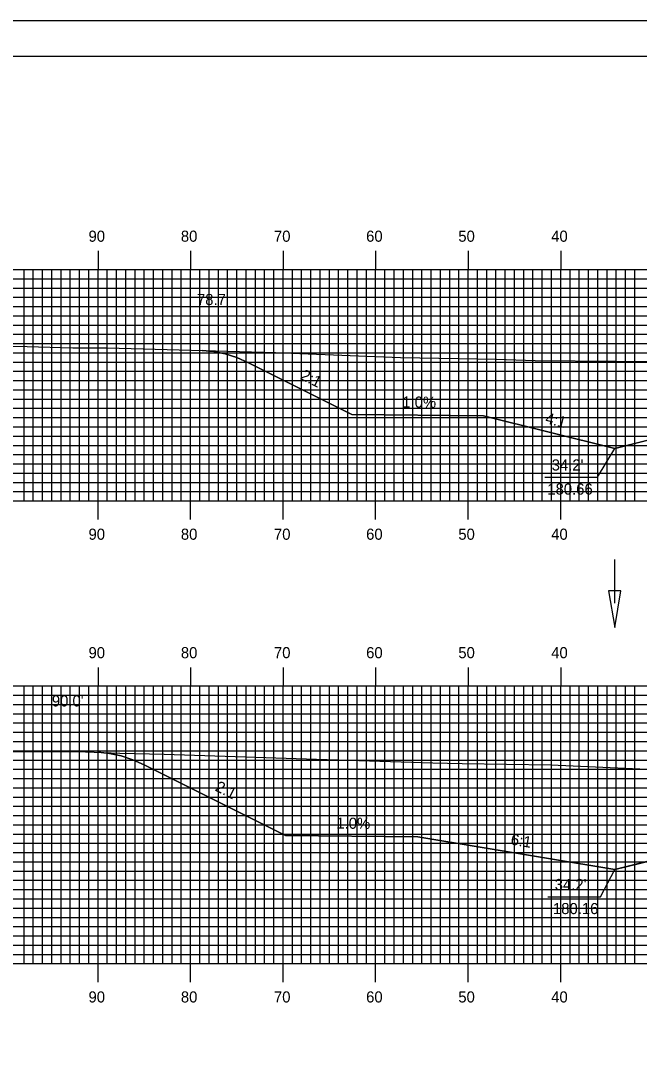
# Model space of a CAD drawing. Extents: x 1797207 to 1797550, y 442591 to 442811.
# Drawn here: x 1797274.6 to 1797341.4, y 442698.3 to 442810.5 of the extents above; entities that cross this region are included whole.
import ezdxf

# ---------------------------------------------------------------- set-up
doc = ezdxf.new("R2010")
doc.units = 0
for name, color, linetype in [('ANNOTATION', 7, 'Continuous'), ('BORDER', 7, 'Continuous'), ('D_Drainage_Ditch_Line', 7, 'Continuous'), ('D_Roadway_Centerline', 7, 'Continuous'), ('D_Roadway_SlopeLines', 7, 'Continuous'), ('D_Text_Standard', 7, 'Continuous'), ('H_V ANNOTATION', 7, 'Continuous'), ('MAJOR', 7, 'Continuous'), ('MINOR', 7, 'Continuous'), ('PLOT BOUNDARY', 7, 'Continuous'), ('S_Roadway_Centerline', 7, 'Continuous')]:
    doc.layers.add(name, color=color, linetype=linetype)

msp = doc.modelspace()

# ---------------------------------------------------------------- linework, layer by layer
at = {"layer": 'ANNOTATION'}
for points in [[(1797331.21, 442761.23), (1797336.9, 442761.23), (1797338.76, 442764.33)], [(1797331.55, 442715.89), (1797337.24, 442715.89), (1797338.76, 442718.83)]]:
    msp.add_lwpolyline(points, dxfattribs=at)
at = {"layer": 'BORDER'}
msp.add_lwpolyline([(1797223.33, 442596.67), (1797543.33, 442596.67), (1797543.33, 442806.67), (1797223.33, 442806.67)], close=True, dxfattribs=at)
at = {"layer": 'D_Drainage_Ditch_Line'}
msp.add_line((1797338.76, 442747.63), (1797338.76, 442752.33), dxfattribs=at)
msp.add_lwpolyline([(1797339.41, 442748.94), (1797338.1, 442748.94), (1797338.76, 442745)], close=True, dxfattribs=at)
at = {"layer": 'D_Roadway_Centerline'}
for points in [[(1797294.18, 442774.92), (1797295.43, 442774.81), (1797296.68, 442774.55), (1797297.93, 442774.15), (1797299.18, 442773.6), (1797310.36, 442768.01), (1797324.58, 442767.87), (1797338.76, 442764.33), (1797342.76, 442765.33), (1797352.93, 442767.87), (1797360.93, 442768.19), (1797372.93, 442767.95), (1797384.93, 442767.71), (1797392.93, 442767.39), (1797403.11, 442764.85), (1797407.11, 442763.85), (1797421.28, 442767.39), (1797440.76, 442767.58), (1797446.68, 442770.54), (1797447.93, 442771.08), (1797449.18, 442771.45), (1797450.43, 442771.65), (1797451.68, 442771.68)], [(1797282.93, 442731.5), (1797284.18, 442731.38), (1797285.43, 442731.11), (1797286.68, 442730.7), (1797287.93, 442730.15), (1797303.2, 442722.51), (1797317.5, 442722.37), (1797338.76, 442718.83), (1797342.76, 442719.83), (1797352.93, 442722.37), (1797360.93, 442722.69), (1797372.93, 442722.45), (1797384.93, 442722.21), (1797392.93, 442721.89)]]:
    msp.add_lwpolyline(points, dxfattribs=at)
at = {"layer": 'D_Roadway_SlopeLines'}
for points in [[(1797324.58, 442767.87), (1797310.36, 442768.01), (1797299.18, 442773.6), (1797297.93, 442774.15), (1797296.68, 442774.55), (1797295.43, 442774.81), (1797294.18, 442774.92)], [(1797338.76, 442764.33), (1797324.58, 442767.87)], [(1797352.93, 442767.87), (1797338.76, 442764.33)], [(1797317.5, 442722.37), (1797303.2, 442722.51), (1797287.93, 442730.15), (1797286.68, 442730.7), (1797285.43, 442731.11), (1797284.18, 442731.38), (1797282.93, 442731.5)], [(1797338.76, 442718.83), (1797317.5, 442722.37)], [(1797352.93, 442722.37), (1797338.76, 442718.83)]]:
    msp.add_lwpolyline(points, dxfattribs=at)
at = {"layer": 'MAJOR'}
for p, q in [((1797282.93, 442785.67), (1797282.93, 442783.67)), ((1797292.93, 442785.67), (1797292.93, 442783.67)), ((1797302.93, 442785.67), (1797302.93, 442783.67)), ((1797312.93, 442785.67), (1797312.93, 442783.67)), ((1797322.93, 442785.67), (1797322.93, 442783.67)), ((1797332.93, 442785.67), (1797332.93, 442783.67)), ((1797232.93, 442783.67), (1797512.93, 442783.67)), ((1797232.93, 442783.67), (1797512.93, 442783.67)), ((1797282.93, 442758.67), (1797282.93, 442783.67)), ((1797292.93, 442758.67), (1797292.93, 442783.67)), ((1797302.93, 442758.67), (1797302.93, 442783.67)), ((1797312.93, 442758.67), (1797312.93, 442783.67)), ((1797322.93, 442758.67), (1797322.93, 442783.67)), ((1797332.93, 442758.67), (1797332.93, 442783.67)), ((1797232.93, 442778.67), (1797512.93, 442778.67)), ((1797232.93, 442773.67), (1797512.93, 442773.67)), ((1797232.93, 442768.67), (1797512.93, 442768.67)), ((1797232.93, 442763.67), (1797512.93, 442763.67)), ((1797232.93, 442758.67), (1797512.93, 442758.67)), ((1797232.93, 442758.67), (1797512.93, 442758.67)), ((1797282.93, 442756.66), (1797282.93, 442758.67)), ((1797292.93, 442756.66), (1797292.93, 442758.67)), ((1797302.93, 442756.66), (1797302.93, 442758.67)), ((1797312.93, 442756.66), (1797312.93, 442758.67)), ((1797322.93, 442756.66), (1797322.93, 442758.67)), ((1797332.93, 442756.66), (1797332.93, 442758.67)), ((1797282.93, 442740.67), (1797282.93, 442738.67)), ((1797292.93, 442740.67), (1797292.93, 442738.67)), ((1797302.93, 442740.67), (1797302.93, 442738.67)), ((1797312.93, 442740.67), (1797312.93, 442738.67)), ((1797322.93, 442740.67), (1797322.93, 442738.67)), ((1797332.93, 442740.67), (1797332.93, 442738.67)), ((1797232.93, 442738.67), (1797512.93, 442738.67)), ((1797232.93, 442738.67), (1797512.93, 442738.67)), ((1797282.93, 442708.67), (1797282.93, 442738.67)), ((1797292.93, 442708.67), (1797292.93, 442738.67)), ((1797302.93, 442708.67), (1797302.93, 442738.67)), ((1797312.93, 442708.67), (1797312.93, 442738.67)), ((1797322.93, 442708.67), (1797322.93, 442738.67)), ((1797332.93, 442708.67), (1797332.93, 442738.67)), ((1797232.93, 442733.67), (1797512.93, 442733.67)), ((1797232.93, 442728.67), (1797512.93, 442728.67)), ((1797232.93, 442723.67), (1797512.93, 442723.67)), ((1797232.93, 442718.67), (1797512.93, 442718.67)), ((1797232.93, 442713.67), (1797512.93, 442713.67)), ((1797232.93, 442708.67), (1797512.93, 442708.67)), ((1797232.93, 442708.67), (1797512.93, 442708.67)), ((1797282.93, 442706.66), (1797282.93, 442708.67)), ((1797292.93, 442706.66), (1797292.93, 442708.67)), ((1797302.93, 442706.66), (1797302.93, 442708.67)), ((1797312.93, 442706.66), (1797312.93, 442708.67)), ((1797322.93, 442706.66), (1797322.93, 442708.67)), ((1797332.93, 442706.66), (1797332.93, 442708.67))]:
    msp.add_line(p, q, dxfattribs=at)
at = {"layer": 'MINOR'}
for p, q in [((1797274.93, 442758.67), (1797274.93, 442783.67)), ((1797275.93, 442758.67), (1797275.93, 442783.67)), ((1797276.93, 442758.67), (1797276.93, 442783.67)), ((1797277.93, 442758.67), (1797277.93, 442783.67)), ((1797278.93, 442758.67), (1797278.93, 442783.67)), ((1797279.93, 442758.67), (1797279.93, 442783.67)), ((1797280.93, 442758.67), (1797280.93, 442783.67)), ((1797281.93, 442758.67), (1797281.93, 442783.67)), ((1797283.93, 442758.67), (1797283.93, 442783.67)), ((1797284.93, 442758.67), (1797284.93, 442783.67)), ((1797285.93, 442758.67), (1797285.93, 442783.67)), ((1797286.93, 442758.67), (1797286.93, 442783.67)), ((1797287.93, 442758.67), (1797287.93, 442783.67)), ((1797288.93, 442758.67), (1797288.93, 442783.67)), ((1797289.93, 442758.67), (1797289.93, 442783.67)), ((1797290.93, 442758.67), (1797290.93, 442783.67)), ((1797291.93, 442758.67), (1797291.93, 442783.67)), ((1797293.93, 442758.67), (1797293.93, 442783.67)), ((1797294.93, 442758.67), (1797294.93, 442783.67)), ((1797295.93, 442758.67), (1797295.93, 442783.67)), ((1797296.93, 442758.67), (1797296.93, 442783.67)), ((1797297.93, 442758.67), (1797297.93, 442783.67)), ((1797298.93, 442758.67), (1797298.93, 442783.67)), ((1797299.93, 442758.67), (1797299.93, 442783.67)), ((1797300.93, 442758.67), (1797300.93, 442783.67)), ((1797301.93, 442758.67), (1797301.93, 442783.67)), ((1797303.93, 442758.67), (1797303.93, 442783.67)), ((1797304.93, 442758.67), (1797304.93, 442783.67)), ((1797305.93, 442758.67), (1797305.93, 442783.67)), ((1797306.93, 442758.67), (1797306.93, 442783.67)), ((1797307.93, 442758.67), (1797307.93, 442783.67)), ((1797308.93, 442758.67), (1797308.93, 442783.67)), ((1797309.93, 442758.67), (1797309.93, 442783.67)), ((1797310.93, 442758.67), (1797310.93, 442783.67)), ((1797311.93, 442758.67), (1797311.93, 442783.67)), ((1797313.93, 442758.67), (1797313.93, 442783.67)), ((1797314.93, 442758.67), (1797314.93, 442783.67)), ((1797315.93, 442758.67), (1797315.93, 442783.67)), ((1797316.93, 442758.67), (1797316.93, 442783.67)), ((1797317.93, 442758.67), (1797317.93, 442783.67)), ((1797318.93, 442758.67), (1797318.93, 442783.67)), ((1797319.93, 442758.67), (1797319.93, 442783.67)), ((1797320.93, 442758.67), (1797320.93, 442783.67)), ((1797321.93, 442758.67), (1797321.93, 442783.67)), ((1797323.93, 442758.67), (1797323.93, 442783.67)), ((1797324.93, 442758.67), (1797324.93, 442783.67)), ((1797325.93, 442758.67), (1797325.93, 442783.67)), ((1797326.93, 442758.67), (1797326.93, 442783.67)), ((1797327.93, 442758.67), (1797327.93, 442783.67)), ((1797328.93, 442758.67), (1797328.93, 442783.67)), ((1797329.93, 442758.67), (1797329.93, 442783.67)), ((1797330.93, 442758.67), (1797330.93, 442783.67)), ((1797331.93, 442758.67), (1797331.93, 442783.67)), ((1797333.93, 442758.67), (1797333.93, 442783.67)), ((1797334.93, 442758.67), (1797334.93, 442783.67)), ((1797335.93, 442758.67), (1797335.93, 442783.67)), ((1797336.93, 442758.67), (1797336.93, 442783.67)), ((1797337.93, 442758.67), (1797337.93, 442783.67)), ((1797338.93, 442758.67), (1797338.93, 442783.67)), ((1797339.93, 442758.67), (1797339.93, 442783.67)), ((1797340.93, 442758.67), (1797340.93, 442783.67)), ((1797232.93, 442782.67), (1797512.93, 442782.67)), ((1797232.93, 442781.67), (1797512.93, 442781.67)), ((1797232.93, 442780.67), (1797512.93, 442780.67)), ((1797232.93, 442779.67), (1797512.93, 442779.67)), ((1797232.93, 442777.67), (1797512.93, 442777.67)), ((1797232.93, 442776.67), (1797512.93, 442776.67)), ((1797232.93, 442775.67), (1797512.93, 442775.67)), ((1797232.93, 442774.67), (1797512.93, 442774.67)), ((1797232.93, 442772.67), (1797512.93, 442772.67)), ((1797232.93, 442771.67), (1797512.93, 442771.67)), ((1797232.93, 442770.67), (1797512.93, 442770.67)), ((1797232.93, 442769.67), (1797512.93, 442769.67)), ((1797232.93, 442767.67), (1797512.93, 442767.67)), ((1797232.93, 442766.67), (1797512.93, 442766.67)), ((1797232.93, 442765.67), (1797512.93, 442765.67)), ((1797232.93, 442764.67), (1797512.93, 442764.67)), ((1797232.93, 442762.67), (1797512.93, 442762.67)), ((1797232.93, 442761.67), (1797512.93, 442761.67)), ((1797232.93, 442760.67), (1797512.93, 442760.67)), ((1797232.93, 442759.67), (1797512.93, 442759.67)), ((1797274.93, 442708.67), (1797274.93, 442738.67)), ((1797275.93, 442708.67), (1797275.93, 442738.67)), ((1797276.93, 442708.67), (1797276.93, 442738.67)), ((1797277.93, 442708.67), (1797277.93, 442738.67)), ((1797278.93, 442708.67), (1797278.93, 442738.67)), ((1797279.93, 442708.67), (1797279.93, 442738.67)), ((1797280.93, 442708.67), (1797280.93, 442738.67)), ((1797281.93, 442708.67), (1797281.93, 442738.67)), ((1797283.93, 442708.67), (1797283.93, 442738.67)), ((1797284.93, 442708.67), (1797284.93, 442738.67)), ((1797285.93, 442708.67), (1797285.93, 442738.67)), ((1797286.93, 442708.67), (1797286.93, 442738.67)), ((1797287.93, 442708.67), (1797287.93, 442738.67)), ((1797288.93, 442708.67), (1797288.93, 442738.67)), ((1797289.93, 442708.67), (1797289.93, 442738.67)), ((1797290.93, 442708.67), (1797290.93, 442738.67)), ((1797291.93, 442708.67), (1797291.93, 442738.67)), ((1797293.93, 442708.67), (1797293.93, 442738.67)), ((1797294.93, 442708.67), (1797294.93, 442738.67)), ((1797295.93, 442708.67), (1797295.93, 442738.67)), ((1797296.93, 442708.67), (1797296.93, 442738.67)), ((1797297.93, 442708.67), (1797297.93, 442738.67)), ((1797298.93, 442708.67), (1797298.93, 442738.67)), ((1797299.93, 442708.67), (1797299.93, 442738.67)), ((1797300.93, 442708.67), (1797300.93, 442738.67)), ((1797301.93, 442708.67), (1797301.93, 442738.67)), ((1797303.93, 442708.67), (1797303.93, 442738.67)), ((1797304.93, 442708.67), (1797304.93, 442738.67)), ((1797305.93, 442708.67), (1797305.93, 442738.67)), ((1797306.93, 442708.67), (1797306.93, 442738.67)), ((1797307.93, 442708.67), (1797307.93, 442738.67)), ((1797308.93, 442708.67), (1797308.93, 442738.67)), ((1797309.93, 442708.67), (1797309.93, 442738.67)), ((1797310.93, 442708.67), (1797310.93, 442738.67)), ((1797311.93, 442708.67), (1797311.93, 442738.67)), ((1797313.93, 442708.67), (1797313.93, 442738.67)), ((1797314.93, 442708.67), (1797314.93, 442738.67)), ((1797315.93, 442708.67), (1797315.93, 442738.67)), ((1797316.93, 442708.67), (1797316.93, 442738.67)), ((1797317.93, 442708.67), (1797317.93, 442738.67)), ((1797318.93, 442708.67), (1797318.93, 442738.67)), ((1797319.93, 442708.67), (1797319.93, 442738.67)), ((1797320.93, 442708.67), (1797320.93, 442738.67)), ((1797321.93, 442708.67), (1797321.93, 442738.67)), ((1797323.93, 442708.67), (1797323.93, 442738.67)), ((1797324.93, 442708.67), (1797324.93, 442738.67)), ((1797325.93, 442708.67), (1797325.93, 442738.67)), ((1797326.93, 442708.67), (1797326.93, 442738.67)), ((1797327.93, 442708.67), (1797327.93, 442738.67)), ((1797328.93, 442708.67), (1797328.93, 442738.67)), ((1797329.93, 442708.67), (1797329.93, 442738.67)), ((1797330.93, 442708.67), (1797330.93, 442738.67)), ((1797331.93, 442708.67), (1797331.93, 442738.67)), ((1797333.93, 442708.67), (1797333.93, 442738.67)), ((1797334.93, 442708.67), (1797334.93, 442738.67)), ((1797335.93, 442708.67), (1797335.93, 442738.67)), ((1797336.93, 442708.67), (1797336.93, 442738.67)), ((1797337.93, 442708.67), (1797337.93, 442738.67)), ((1797338.93, 442708.67), (1797338.93, 442738.67)), ((1797339.93, 442708.67), (1797339.93, 442738.67)), ((1797340.93, 442708.67), (1797340.93, 442738.67)), ((1797232.93, 442737.67), (1797512.93, 442737.67)), ((1797232.93, 442736.67), (1797512.93, 442736.67)), ((1797232.93, 442735.67), (1797512.93, 442735.67)), ((1797232.93, 442734.67), (1797512.93, 442734.67)), ((1797232.93, 442732.67), (1797512.93, 442732.67)), ((1797232.93, 442731.67), (1797512.93, 442731.67)), ((1797232.93, 442730.67), (1797512.93, 442730.67)), ((1797232.93, 442729.67), (1797512.93, 442729.67)), ((1797232.93, 442727.67), (1797512.93, 442727.67)), ((1797232.93, 442726.67), (1797512.93, 442726.67)), ((1797232.93, 442725.67), (1797512.93, 442725.67)), ((1797232.93, 442724.67), (1797512.93, 442724.67)), ((1797232.93, 442722.67), (1797512.93, 442722.67)), ((1797232.93, 442721.67), (1797512.93, 442721.67)), ((1797232.93, 442720.67), (1797512.93, 442720.67)), ((1797232.93, 442719.67), (1797512.93, 442719.67)), ((1797232.93, 442717.67), (1797512.93, 442717.67)), ((1797232.93, 442716.67), (1797512.93, 442716.67)), ((1797232.93, 442715.67), (1797512.93, 442715.67)), ((1797232.93, 442714.67), (1797512.93, 442714.67)), ((1797232.93, 442712.67), (1797512.93, 442712.67)), ((1797232.93, 442711.67), (1797512.93, 442711.67)), ((1797232.93, 442710.67), (1797512.93, 442710.67)), ((1797232.93, 442709.67), (1797512.93, 442709.67))]:
    msp.add_line(p, q, dxfattribs=at)
at = {"layer": 'PLOT BOUNDARY'}
msp.add_lwpolyline([(1797207.14, 442590.55), (1797547.14, 442590.55), (1797547.14, 442810.55), (1797207.14, 442810.55)], close=True, dxfattribs=at)
at = {"layer": 'S_Roadway_Centerline'}
for points in [[(1797232.93, 442776.04), (1797233.61, 442776.01), (1797243.32, 442775.74), (1797249.59, 442775.69), (1797263.52, 442775.6), (1797268.45, 442775.48), (1797275.26, 442775.35), (1797280.22, 442775.22), (1797283.93, 442775.19), (1797302.11, 442774.71), (1797303.06, 442774.67), (1797303.83, 442774.62), (1797315.6, 442774.15), (1797325.99, 442773.97), (1797330.16, 442773.85), (1797338.85, 442773.76), (1797346.65, 442773.7)], [(1797232.93, 442731.74), (1797235.39, 442731.72), (1797240.06, 442731.69), (1797249.55, 442731.92), (1797260.61, 442731.63), (1797264.02, 442731.59), (1797281.56, 442731.56), (1797285.28, 442731.4), (1797290.06, 442731.29), (1797306.55, 442730.77), (1797319.12, 442730.37), (1797322.28, 442730.3), (1797331.86, 442730.14), (1797343.1, 442729.66)]]:
    msp.add_lwpolyline(points, dxfattribs=at)

# ---------------------------------------------------------------- texts
at = {"layer": 'ANNOTATION'}
for s, rotation, p in [('2:1', 333.4349, (1797304.7, 442771.87)), ('1.0%', 359.4271, (1797315.8, 442768.76)), ('4:1', 345.9638, (1797331.18, 442767.08)), ('2:1', 333.4349, (1797295.5, 442727.4)), ('1.0%', 359.4271, (1797308.68, 442723.26)), ('6:1', 350.5377, (1797327.46, 442721.54))]:
    msp.add_text(s, height=1.2, rotation=rotation, dxfattribs=at).set_placement(p)
for s, p in [("34.2'", (1797331.95, 442761.95)), ('180.66', (1797331.48, 442759.35)), ("34.2'", (1797332.28, 442716.62)), ('180.16', (1797332.09, 442714.02))]:
    msp.add_text(s, height=1.2, dxfattribs=at).set_placement(p)
at = {"layer": 'D_Text_Standard'}
for s, p in [("78.7'", (1797293.62, 442779.83)), ("90.0'", (1797277.94, 442736.46))]:
    msp.add_text(s, height=1.2, dxfattribs=at).set_placement(p)
at = {"layer": 'H_V ANNOTATION'}
for s, p in [('90', (1797281.9, 442786.67)), ('80', (1797291.88, 442786.67)), ('70', (1797301.94, 442786.67)), ('60', (1797311.9, 442786.67)), ('50', (1797321.86, 442786.67)), ('40', (1797331.9, 442786.67)), ('90', (1797281.9, 442754.47)), ('80', (1797291.88, 442754.47)), ('70', (1797301.94, 442754.47)), ('60', (1797311.9, 442754.47)), ('50', (1797321.86, 442754.47)), ('40', (1797331.9, 442754.47)), ('90', (1797281.9, 442741.67)), ('80', (1797291.88, 442741.67)), ('70', (1797301.94, 442741.67)), ('60', (1797311.9, 442741.67)), ('50', (1797321.86, 442741.67)), ('40', (1797331.9, 442741.67)), ('90', (1797281.9, 442704.47)), ('80', (1797291.88, 442704.47)), ('70', (1797301.94, 442704.47)), ('60', (1797311.9, 442704.47)), ('50', (1797321.86, 442704.47)), ('40', (1797331.9, 442704.47))]:
    msp.add_text(s, height=1.2, dxfattribs=at).set_placement(p)

doc.saveas('drawing.dxf')
